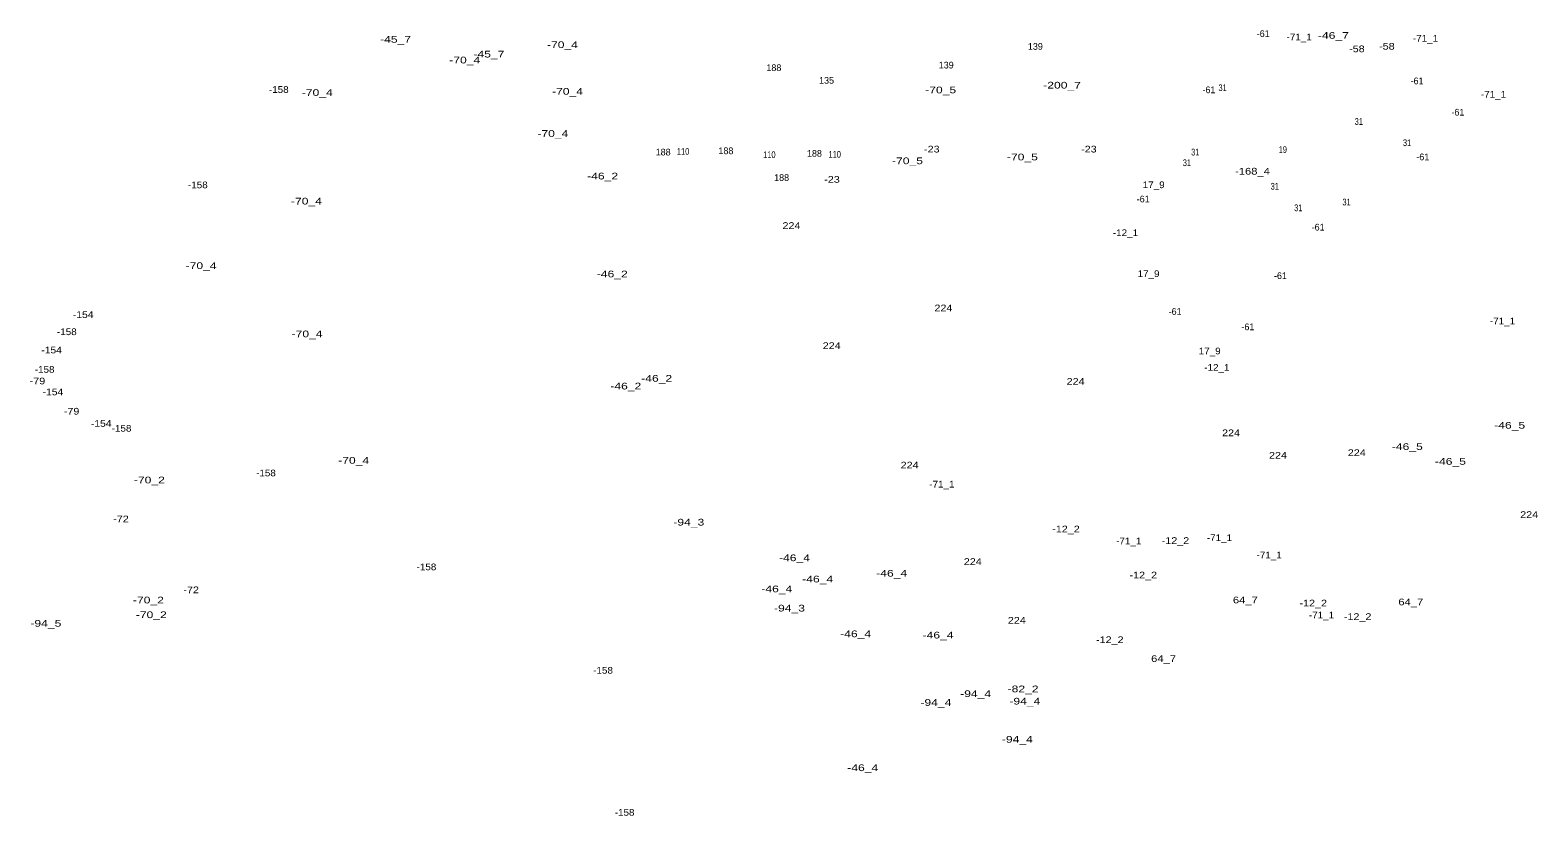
# Model space of a CAD drawing. Extents: x -662996 to -659766, y -998554 to -993949.
# Drawn here: x -661500 to -660600, y -998332 to -997863 of the extents above; entities that cross this region are included whole.
import ezdxf
from ezdxf.enums import TextEntityAlignment as Align

# ---------------------------------------------------------------- set-up
doc = ezdxf.new("R2010")
doc.units = 0
doc.header["$LTSCALE"] = 1.6
doc.layers.add('24', color=7, linetype='Continuous')

msp = doc.modelspace()

# ---------------------------------------------------------------- texts
at = {"layer": '24'}
for s, width, p in [('-45_7', 1.35, (-661281.689, -997870.54)), ('-70_4', 1.35, (-661182.15, -997873.76)), ('-71_1', 1.1, (-660742.691, -997869.13)), ('-46_7', 1.35, (-660722.27, -997868.24)), ('-71_1', 1.1, (-660667.291, -997869.89)), ('-70_4', 1.35, (-661240.42, -997882.91)), ('-45_7', 1.35, (-661226, -997879.37)), ('-58', 1.2, (-660708.27, -997876.22)), ('-58', 1.2, (-660690.37, -997874.69)), ('-158', 1.1, (-661351.351, -997900.47)), ('-70_5', 1.35, (-660956.54, -997900.72)), ('-200_7', 1.35, (-660884.11, -997897.89)), ('31', 0.8, (-660788.35, -997899.39)), ('-70_4', 1.35, (-661328.39, -997902.29)), ('-70_4', 1.35, (-661179.11, -997901.57)), ('-71_1', 1.1, (-660626.731, -997903.29)), ('-70_4', 1.35, (-661187.86, -997926.7)), ('31', 0.8, (-660707.13, -997919.55)), ('110', 0.8, (-661110.18, -997937.4)), ('-23', 1.2, (-660961.84, -997936.02)), ('-23', 1.2, (-660868.14, -997936.02)), ('19', 0.8, (-660752.451, -997936.27)), ('31', 0.8, (-660678.329, -997932.23)), ('110', 0.8, (-661058.72, -997939.32)), ('110', 0.8, (-661019.74, -997939.12)), ('-70_5', 1.35, (-660976.34, -997943)), ('-70_5', 1.35, (-660907.79, -997940.72)), ('31', 0.8, (-660809.66, -997944.14)), ('31', 0.8, (-660804.669, -997937.8)), ('-46_2', 1.35, (-661158.19, -997952.1)), ('-23', 1.2, (-661021.36, -997954.08)), ('-168_4', 1.25, (-660770.56, -997949.19)), ('-158', 1.1, (-661399.64, -997957.36)), ('17_9', 1.1, (-660829.481, -997957.29)), ('31', 0.8, (-660757.25, -997958.16)), ('-70_4', 1.35, (-661334.86, -997967.05)), ('31', 0.8, (-660743.23, -997971.03)), ('31', 0.8, (-660714.429, -997967.57)), ('224', 1.2, (-661045.53, -997981.6)), ('-12_1', 1.1, (-660846.319, -997985.9)), ('-70_4', 1.35, (-661397.69, -998005.53)), ('-46_2', 1.35, (-661152.43, -998010.5)), ('17_9', 1.1, (-660832.551, -998010.3)), ('-154', 1.15, (-661468.04, -998034.7)), ('224', 1.2, (-660954.89, -998030.74)), ('-158', 1.1, (-661477.791, -998044.94)), ('-71_1', 1.1, (-660621.4, -998038.53)), ('-70_4', 1.35, (-661334.48, -998046.21)), ('224', 1.2, (-661021.54, -998053.22)), ('-154', 1.15, (-661486.86, -998055.83)), ('17_9', 1.1, (-660796.071, -998056.4)), ('-158', 1.1, (-661491.03, -998067.38)), ('-12_1', 1.1, (-660791.79, -998066.19)), ('-79', 1.2, (-661495.309, -998074.28)), ('-154', 1.15, (-661486.09, -998080.8)), ('-46_2', 1.35, (-661144.36, -998077.34)), ('-46_2', 1.35, (-661125.93, -998072.73)), ('224', 1.2, (-660876.059, -998074.55)), ('-79', 1.2, (-661474.949, -998092.34)), ('-154', 1.15, (-661457.29, -998099.62)), ('-158', 1.1, (-661445.14, -998102.5)), ('224', 1.2, (-660783.329, -998105.22)), ('-46_5', 1.35, (-660617.13, -998100.73)), ('224', 1.2, (-660708.309, -998117.03)), ('-46_5', 1.35, (-660678.19, -998113.41)), ('-70_4', 1.35, (-661306.68, -998121.64)), ('224', 1.2, (-660975.079, -998124.46)), ('224', 1.2, (-660755.34, -998118.63)), ('-46_5', 1.35, (-660652.46, -998122.25)), ('-70_2', 1.35, (-661428.55, -998133.33)), ('-158', 1.1, (-661359.01, -998129.16)), ('-71_1', 1.1, (-660955.801, -998135.82)), ('-72', 1.2, (-661445.5, -998156.57)), ('-94_3', 1.35, (-661106.77, -998158.5)), ('224', 1.2, (-660605.49, -998153.98)), ('-12_2', 1.2, (-660881.77, -998162.56)), ('-71_1', 1.1, (-660844.37, -998169.7)), ('-12_2', 1.2, (-660816.48, -998169.47)), ('-71_1', 1.1, (-660790.291, -998167.8)), ('-46_4', 1.35, (-661043.73, -998179.75)), ('-71_1', 1.1, (-660760.591, -998178.08)), ('-158', 1.1, (-661263.27, -998185.17)), ('-46_4', 1.35, (-660985.74, -998188.97)), ('224', 1.2, (-660937.37, -998181.98)), ('-46_4', 1.35, (-661054.28, -998198.3)), ('-46_4', 1.35, (-661029.9, -998192.43)), ('-12_2', 1.2, (-660835.679, -998190.03)), ('-70_2', 1.35, (-661429.12, -998204.95)), ('-72', 1.2, (-661403.62, -998198.86)), ('64_7', 1.25, (-660774.8, -998204.92)), ('-12_2', 1.2, (-660734.299, -998206.74)), ('64_7', 1.25, (-660676.11, -998206.07)), ('-70_2', 1.35, (-661427.41, -998213.71)), ('-94_3', 1.35, (-661046.72, -998209.77)), ('-71_1', 1.1, (-660729.361, -998213.89)), ('-12_2', 1.2, (-660707.809, -998214.8)), ('-94_5', 1.35, (-661490.29, -998218.83)), ('-46_4', 1.35, (-661007.25, -998225.08)), ('224', 1.2, (-660911.1, -998217.03)), ('-46_4', 1.35, (-660958.09, -998225.85)), ('-12_2', 1.2, (-660855.65, -998228.59)), ('64_7', 1.25, (-660823.57, -998239.88)), ('-158', 1.1, (-661157.941, -998246.86)), ('-94_4', 1.35, (-660935.679, -998260.78)), ('-82_2', 1.35, (-660907.38, -998257.93)), ('-94_4', 1.35, (-660959.39, -998266.03)), ('-94_4', 1.35, (-660906.329, -998265.25)), ('-94_4', 1.35, (-660910.799, -998288)), ('-46_4', 1.35, (-661003.02, -998304.94)), ('-158', 1.1, (-661145.071, -998331.57))]:
    msp.add_text(s, height=4, dxfattribs=dict(at, width=width)).set_placement(p, align=Align.CENTER)
for s, p in [('-61', (-660764.15, -997867.13)), ('139', (-660900.051, -997874.77)), ('188', (-661056.03, -997887.47)), ('139', (-660953.231, -997885.91)), ('135', (-661024.61, -997895.02)), ('-61', (-660796.52, -997900.65)), ('-61', (-660672.37, -997895.32)), ('-61', (-660648, -997913.99)), ('188', (-661084.64, -997937.02)), ('188', (-661122.079, -997937.79)), ('188', (-661031.84, -997938.56)), ('-61', (-660668.95, -997940.65)), ('188', (-661051.419, -997952.97)), ('-61', (-660835.74, -997965.8)), ('-61', (-660731.4, -997982.56)), ('-61', (-660753.87, -998011.51)), ('-61', (-660816.7, -998032.84)), ('-61', (-660773.29, -998041.99))]:
    msp.add_text(s, height=4, dxfattribs=at).set_placement(p, align=Align.CENTER)

doc.saveas('drawing.dxf')
